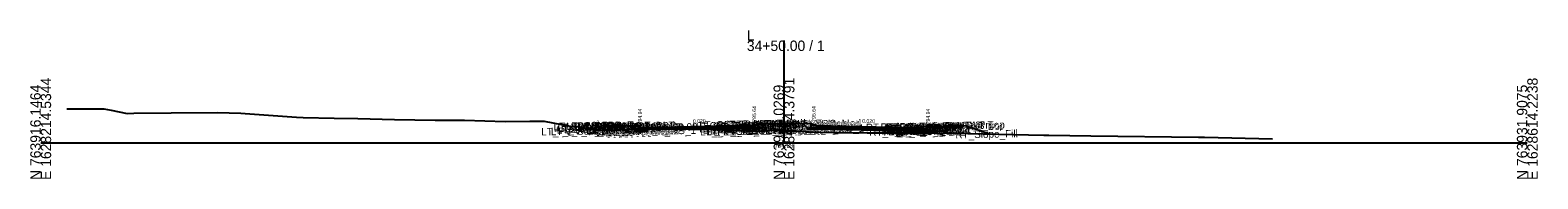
# Model space of a CAD drawing. Extents: x -26 to 4403, y -510 to 9556.
# Drawn here: x 1997.2 to 2402.8, y 4490.3 to 4530.3 of the extents above; entities that cross this region are included whole.
import ezdxf

# ---------------------------------------------------------------- set-up
doc = ezdxf.new("R2010")
doc.units = 0
for name, color, linetype in [('Default', 7, 'Continuous'), ('Exist CMT Pavement', 7, 'Continuous'), ('Exist Cross Section Cell', 7, 'Continuous'), ('Exist XS Center Line Elevation Label', 7, 'Continuous'), ('Exist XS Ground Line', 7, 'Continuous'), ('Prop CMT Conc Surface', 7, 'Continuous'), ('Prop CMT Concrete Structures', 7, 'Continuous'), ('Prop CMT Pvmt Course 1', 7, 'Continuous'), ('Prop CMT Pvmt Course 1 CG', 7, 'Continuous'), ('Prop CMT Pvmt Course 2', 7, 'Continuous'), ('Prop CMT Pvmt Course 2 Wedge', 7, 'Continuous'), ('Prop CMT Pvmt Course 3', 7, 'Continuous'), ('Prop CMT Pvmt Course 3 Wedge', 7, 'Continuous'), ('Prop CMT Pvmt Surface', 7, 'Continuous'), ('Prop CMT Slope Grass', 7, 'Continuous'), ('Prop CMT Subgrade Earthwork', 7, 'Continuous'), ('Prop XS Hydro Elevations', 7, 'Continuous'), ('Prop XS SE Text', 7, 'Continuous'), ('Prop XS Side Slope Text', 7, 'Continuous'), ('Scratch_Level_0', 7, 'Continuous')]:
    doc.layers.add(name, color=color, linetype=linetype)

msp = doc.modelspace()

# ---------------------------------------------------------------- linework, layer by layer
at = {"layer": 'Exist CMT Pavement'}
for points in [[(2163.26, 4503.69), (2168.79, 4503.73), (2171.81, 4503.75), (2174.71, 4503.69), (2181.6, 4503.54), (2184.34, 4503.45), (2190.83, 4503.23)], [(2190.83, 4503.23), (2190.83, 4503.23)]]:
    msp.add_lwpolyline(points, dxfattribs=at)
at = {"layer": 'Exist Cross Section Cell'}
for p, q in [((2200, 4500), (2200, 4527.48)), ((2000, 4500), (2200, 4500)), ((2200, 4500), (2400, 4500))]:
    msp.add_line(p, q, dxfattribs=at)
at = {"layer": 'Exist XS Ground Line'}
msp.add_lwpolyline([(2007.04, 4509.15), (2007.6, 4509.11), (2008.05, 4509.1), (2012.66, 4509.09), (2012.97, 4509.1), (2016.98, 4509.12), (2018.93, 4508.76), (2023.24, 4507.91), (2025.05, 4507.94), (2035.09, 4508.04), (2047.58, 4508.14), (2053.83, 4507.97), (2054.98, 4507.87), (2068.86, 4506.89), (2070.66, 4506.83), (2079, 4506.63), (2085.35, 4506.56), (2095.16, 4506.28), (2106.12, 4506.08), (2114.04, 4506.1), (2124.98, 4505.76), (2131.6, 4505.85), (2135.51, 4505.8), (2142.49, 4504.45), (2144.81, 4504.29), (2149.19, 4503.49), (2149.71, 4503.26), (2158.03, 4503.55), (2161.61, 4503.68), (2168.79, 4503.73), (2171.81, 4503.75), (2174.71, 4503.69), (2181.6, 4503.54), (2184.34, 4503.45), (2190.83, 4503.23), (2191.5, 4503.16), (2191.98, 4503.09), (2196.97, 4503.41), (2199.37, 4503.37), (2200, 4503.29), (2202.5, 4503), (2205.56, 4503.13), (2206.69, 4502.95), (2213.19, 4502.77), (2214.38, 4502.74), (2222.34, 4502.71), (2237.03, 4502.71), (2238.11, 4502.71), (2239.53, 4502.69), (2241.3, 4502.65), (2269.94, 4502.03), (2271.25, 4502.01), (2282.58, 4501.88), (2311.49, 4501.55), (2312.57, 4501.52), (2313.17, 4501.51), (2331.4, 4501.05)], dxfattribs=at)
at = {"layer": 'Prop CMT Conc Surface'}
for points in [[(2156.75, 4504.53), (2151.75, 4504.63)], [(2161.25, 4503.94), (2161.25, 4504.44), (2160.75, 4504.44)], [(2163.25, 4504.06), (2161.25, 4503.94)], [(2191.25, 4504.62), (2192, 4504.64), (2192, 4504.8), (2192.76, 4505.05)], [(2208.75, 4504.62), (2208, 4504.64), (2208, 4504.8), (2207.24, 4505.05)], [(2236.75, 4504.06), (2238.75, 4503.94)], [(2238.75, 4503.94), (2238.75, 4504.44), (2239.25, 4504.44)], [(2243.25, 4504.53), (2248.25, 4504.63)]]:
    msp.add_lwpolyline(points, dxfattribs=at)
at = {"layer": 'Prop CMT Concrete Structures'}
for points in [[(2151.75, 4504.3), (2151.75, 4504.63)], [(2151.75, 4504.63), (2156.75, 4504.53)], [(2156.75, 4504.2), (2151.75, 4504.3)], [(2156.75, 4504.53), (2156.75, 4504.2)], [(2163.25, 4504.06), (2161.25, 4503.94), (2161.25, 4504.44), (2160.75, 4504.44)], [(2160.75, 4504.44), (2160.75, 4503.43), (2163.25, 4503.48)], [(2163.25, 4503.48), (2163.25, 4504.06)], [(2191.25, 4504.62), (2192, 4504.64), (2192, 4504.8), (2192.76, 4505.05)], [(2191.25, 4504.04), (2191.25, 4504.62)], [(2192.76, 4504.07), (2191.25, 4504.04)], [(2192.76, 4505.05), (2192.76, 4504.07)], [(2208.75, 4504.62), (2208, 4504.64), (2208, 4504.8), (2207.24, 4505.05)], [(2207.24, 4505.05), (2207.24, 4504.07)], [(2207.24, 4504.07), (2208.75, 4504.04)], [(2208.75, 4504.04), (2208.75, 4504.62)], [(2236.75, 4504.06), (2238.75, 4503.94), (2238.75, 4504.44), (2239.25, 4504.44)], [(2239.25, 4504.44), (2239.25, 4503.43), (2236.75, 4503.48)], [(2236.75, 4503.48), (2236.75, 4504.06)], [(2248.25, 4504.63), (2243.25, 4504.53)], [(2243.25, 4504.53), (2243.25, 4504.2)], [(2243.25, 4504.2), (2248.25, 4504.3)], [(2248.25, 4504.3), (2248.25, 4504.63)]]:
    msp.add_lwpolyline(points, dxfattribs=at)
at = {"layer": 'Prop CMT Pvmt Course 1'}
for points in [[(2191.25, 4504.62), (2163.25, 4504.06)], [(2163.25, 4503.81), (2190.83, 4504.36), (2191.25, 4504.37)], [(2163.25, 4504.06), (2163.25, 4503.81), (2163.25, 4503.81)], [(2191.25, 4504.37), (2191.25, 4504.62)], [(2208.75, 4504.62), (2236.75, 4504.06)], [(2208.75, 4504.37), (2208.75, 4504.62)], [(2236.75, 4503.81), (2208.75, 4504.37)], [(2208.75, 4504.37), (2208.75, 4504.37), (2208.75, 4504.37)], [(2236.75, 4504.06), (2236.75, 4503.81)]]:
    msp.add_lwpolyline(points, dxfattribs=at)
at = {"layer": 'Prop CMT Pvmt Course 1 CG'}
for points in [[(2163.25, 4503.48), (2160.25, 4503.42), (2159.91, 4503.08)], [(2159.91, 4503.08), (2163.25, 4503.15)], [(2163.25, 4503.15), (2163.25, 4503.48)], [(2191.25, 4504.04), (2193.26, 4504.08), (2193.59, 4503.75)], [(2191.25, 4503.71), (2191.25, 4504.04)], [(2193.59, 4503.75), (2191.25, 4503.71)], [(2208.75, 4504.04), (2206.74, 4504.08), (2206.41, 4503.75)], [(2206.41, 4503.75), (2208.75, 4503.71)], [(2208.75, 4503.71), (2208.75, 4504.04)], [(2236.75, 4503.48), (2239.75, 4503.42), (2240.09, 4503.08)], [(2236.75, 4503.15), (2236.75, 4503.48)], [(2240.09, 4503.08), (2236.75, 4503.15)]]:
    msp.add_lwpolyline(points, dxfattribs=at)
at = {"layer": 'Prop CMT Pvmt Course 2'}
for points in [[(2163.25, 4503.48), (2163.25, 4503.48), (2163.25, 4503.81), (2163.25, 4503.81)], [(2163.25, 4503.81), (2163.25, 4503.48)], [(2191.25, 4504.37), (2190.83, 4504.36)], [(2190.83, 4504.36), (2190.83, 4504.03)], [(2190.83, 4504.03), (2191.25, 4504.04)], [(2191.25, 4504.04), (2191.25, 4504.37)], [(2208.75, 4504.04), (2208.75, 4504.37)], [(2208.75, 4504.37), (2236.75, 4503.81)], [(2236.75, 4503.48), (2208.75, 4504.04)], [(2236.75, 4503.81), (2236.75, 4503.48)]]:
    msp.add_lwpolyline(points, dxfattribs=at)
at = {"layer": 'Prop CMT Pvmt Course 2 Wedge'}
for points in [[(2163.25, 4503.81), (2168.79, 4503.92), (2171.81, 4503.98), (2174.71, 4504.04), (2181.6, 4504.18), (2184.34, 4504.23), (2190.83, 4504.36)], [(2163.25, 4503.69), (2163.25, 4503.81)], [(2190.83, 4504.03), (2184.34, 4503.9), (2181.6, 4503.85), (2174.71, 4503.71), (2174.23, 4503.7), (2171.81, 4503.75), (2168.79, 4503.73), (2163.26, 4503.69)], [(2190.83, 4504.36), (2190.83, 4504.03), (2190.83, 4504.03)]]:
    msp.add_lwpolyline(points, dxfattribs=at)
at = {"layer": 'Prop CMT Pvmt Course 3'}
for points in [[(2163.25, 4503.48), (2163.25, 4503.48), (2163.25, 4503.15), (2163.25, 4503.15)], [(2163.25, 4503.15), (2163.25, 4503.48)], [(2191.25, 4504.04), (2190.83, 4504.03)], [(2190.83, 4504.03), (2190.83, 4503.7)], [(2190.83, 4503.7), (2191.25, 4503.71)], [(2191.25, 4503.71), (2191.25, 4504.04)], [(2208.75, 4504.04), (2236.75, 4503.48)], [(2208.75, 4503.71), (2208.75, 4504.04)], [(2236.75, 4503.15), (2208.75, 4503.71)], [(2236.75, 4503.48), (2236.75, 4503.15)]]:
    msp.add_lwpolyline(points, dxfattribs=at)
at = {"layer": 'Prop CMT Pvmt Course 3 Wedge'}
for points in [[(2174.23, 4503.7), (2174.71, 4503.71)], [(2190.83, 4503.23), (2184.34, 4503.45), (2181.6, 4503.54), (2174.71, 4503.69), (2174.23, 4503.7)], [(2174.71, 4503.71), (2181.6, 4503.85), (2184.34, 4503.9), (2190.83, 4504.03)], [(2190.83, 4504.03), (2190.83, 4503.23), (2190.83, 4503.23)]]:
    msp.add_lwpolyline(points, dxfattribs=at)
at = {"layer": 'Prop CMT Pvmt Surface'}
for points in [[(2191.25, 4504.62), (2163.25, 4504.06)], [(2208.75, 4504.62), (2236.75, 4504.06)]]:
    msp.add_lwpolyline(points, dxfattribs=at)
at = {"layer": 'Prop CMT Slope Grass'}
for points in [[(2160.75, 4504.44), (2151.25, 4504.63), (2148.31, 4503.65)], [(2192.76, 4505.05), (2200, 4505.2)], [(2207.24, 4505.05), (2200, 4505.2)], [(2239.25, 4504.44), (2248.75, 4504.63), (2255.63, 4502.34)]]:
    msp.add_lwpolyline(points, dxfattribs=at)
at = {"layer": 'Prop CMT Subgrade Earthwork'}
for points in [[(2163.25, 4503.15), (2159.91, 4503.08), (2158.5, 4504.49)], [(2163.25, 4503.15), (2163.26, 4503.69)], [(2163.25, 4503.15), (2163.25, 4503.48)], [(2163.25, 4503.15), (2163.25, 4503.15)], [(2163.25, 4503.15), (2163.25, 4503.15)], [(2191.25, 4503.71), (2190.83, 4503.7)], [(2190.83, 4503.7), (2190.83, 4503.23)], [(2193.59, 4503.75), (2191.25, 4503.71)], [(2191.25, 4503.71), (2191.25, 4503.71)], [(2194.93, 4505.1), (2193.59, 4503.75)], [(2205.07, 4505.1), (2206.41, 4503.75)], [(2206.41, 4503.75), (2208.75, 4503.71)], [(2208.75, 4503.71), (2236.75, 4503.15)], [(2208.75, 4503.71), (2208.75, 4503.71)], [(2208.75, 4503.71), (2208.75, 4503.71)], [(2236.75, 4503.15), (2240.09, 4503.08), (2241.5, 4504.49)], [(2236.75, 4503.15), (2236.75, 4503.15)]]:
    msp.add_lwpolyline(points, dxfattribs=at)

# ---------------------------------------------------------------- texts
at = {"layer": 'Default'}
msp.add_text('-', height=0.0001, dxfattribs=at).set_placement((2000, 4500))
at = {"layer": 'Exist Cross Section Cell'}
for s, p in [('34+50.00 / 1', (2190, 4524.68)), ('L', (2190, 4527.48))]:
    msp.add_text(s, height=2.8, dxfattribs=at).set_placement(p)
for s, p in [('N 763916.1464', (2000, 4490)), ('E 1628214.5344', (2002.8, 4490)), ('N 763924.0269', (2200, 4490)), ('E 1628414.3791', (2202.8, 4490)), ('N 763931.9075', (2400, 4490)), ('E 1628614.2238', (2402.8, 4490))]:
    msp.add_text(s, height=2.8, rotation=90, dxfattribs=at).set_placement(p)
at = {"layer": 'Exist XS Center Line Elevation Label'}
msp.add_text('794.29', height=1.2, dxfattribs=at).set_placement((2197.48, 4498.69))
at = {"layer": 'Prop XS Hydro Elevations'}
for s, p in [('794.94', (2161.75, 4504.94)), ('795.64', (2192.5, 4505.64)), ('795.64', (2208.5, 4505.64)), ('794.94', (2239.25, 4504.94))]:
    msp.add_text(s, height=1, rotation=90, dxfattribs=at).set_placement(p)
at = {"layer": 'Prop XS SE Text'}
for rotation, p in [(1.1458, (2175.48, 4505.31)), (358.8543, (2221.02, 4505.38))]:
    msp.add_text('0.020', height=1, rotation=rotation, dxfattribs=at).set_placement(p)
at = {"layer": 'Prop XS Side Slope Text'}
for rotation, p in [(18.4333, (2148.79, 4504.6)), (341.5634, (2251.68, 4504.45))]:
    msp.add_text('3:1', height=1, rotation=rotation, dxfattribs=at).set_placement(p)
at = {"layer": 'Scratch_Level_0'}
for s, p in [('LT_PV_Sub_Tie_Out', (2134.68, 4501.96)), ('LT_PV_OEEOP_EG', (2137.28, 4502.02)), ('LT_SDWK_Out_Top', (2138.01, 4503.36)), ('LT_SDWK_Out_Bot', (2138.04, 4503.02)), ('LT_Slope_Fill', (2138.85, 4502.46)), ('LT_Sub_Trench_Out_DLT', (2139.09, 4503.1)), ('LT_CSLP_Pnt', (2141.45, 4503.44)), ('34+50.00', (2144.64, 4503.5)), ('LT_SDWK_In_Top', (2144.63, 4503.29)), ('LT_SDWK_In_Bot', (2144.66, 4502.96)), ('LT_CG1_Shelf_Out', (2146.82, 4502.15)), ('LT_CG_Top_Face', (2148.53, 4503.19)), ('LT_CG_Top_BOC', (2149.06, 4503.21)), ('LT_CG_Bot_BOC', (2149.09, 4502.2)), ('LT_Sub_OEOT_CG_1', (2149.49, 4501.87)), ('LT_CG_Top_Gut', (2149.51, 4502.71)), ('LT_Sub_OEOP', (2150.04, 4501.88)), ('34+50.00', (2152.54, 4503.34)), ('LT_Sub_OEEOP', (2152.49, 4501.93)), ('LT_PV2_OEEOP', (2152.58, 4502.6)), ('LT_PV3_OEEOP', (2152.58, 4502.27)), ('LT_CG_Bot_IE', (2153.19, 4502.28)), ('LT_Sub_OEOT', (2153.35, 4501.95)), ('LT_PV2_OEOT', (2153.45, 4502.62)), ('LT_PV3_OEOT', (2153.45, 4502.28)), ('LT_PV1_OEOT', (2154.01, 4502.88)), ('34+50.00', (2155.53, 4502.87)), ('34+50.00', (2165.54, 4503.11)), ('LT_CG_Top_Face_Med', (2175.39, 4503.47)), ('LT_CG_Top_Gut_Med', (2176.37, 4503.33)), ('LT_CG_Top_BOC_Med', (2177.18, 4503.74)), ('LT_CG_Bot_BOC_Med', (2177.21, 4502.76)), ('LT_CG_Bot_IE_Med', (2177.34, 4502.76)), ('LT_PV_Sub_Tie_In', (2177.42, 4501.97)), ('LT_Sub_IEOT_CG_1', (2178.14, 4502.44)), ('LT_PV_IEEOP_EG', (2179.04, 4502)), ('LT_Sub_IEEOP', (2180.71, 4502.49)), ('LT_PV2_IEEOP', (2180.8, 4503.16)), ('LT_PV3_IEEOP', (2180.8, 4502.83)), ('LT_CG1_Shelf_In', (2181.46, 4502.84)), ('LT_Sub_PGL', (2182.39, 4502.53)), ('LT_PV2_PGL', (2182.48, 4503.2)), ('LT_PV3_PGL', (2182.48, 4502.86)), ('LT_PV1_PGL', (2183.05, 4503.46)), ('LT_Sub_DLT_In', (2183.9, 4503.88)), ('LT_Sub_IEOP', (2184.36, 4502.57)), ('34+50.00', (2184.8, 4503.49)), ('MD_Crown Point', (2187.09, 4503.94)), ('34+50.00', (2187.23, 4503.94)), ('RT_CG_Top_Face_Med', (2191.35, 4503.47)), ('RT_CG_Top_BOC_Med', (2191.61, 4503.74)), ('RT_CG_Bot_BOC_Med', (2191.64, 4502.76)), ('34+50.00', (2192.35, 4504.05)), ('RT_CG_Top_Gut_Med', (2192.32, 4503.32)), ('RT_Sub_DLT_In', (2193.99, 4503.88)), ('RT_CG_Bot_IE_Med', (2194.79, 4502.76)), ('RT_CG1_Shelf_In', (2194.89, 4502.84)), ('RT_Sub_IEOT_CG_1', (2195.59, 4502.44)), ('RT_Sub_IEOP', (2197.14, 4502.57)), ('RT_Sub_OEEOP', (2197.94, 4502.49)), ('RT_PV2_OEEOP', (2198.03, 4503.16)), ('RT_PV3_OEEOP', (2198.03, 4502.82)), ('RT_Sub_IEEOP', (2198.58, 4502.5)), ('RT_PV2_IEEOP', (2198.68, 4503.17)), ('34+50.00', (2199.73, 4503.93)), ('RT_Sub_PGL', (2199.84, 4502.53)), ('RT_PV2_PGL', (2199.94, 4503.2)), ('RT_PV1_PGL', (2200.5, 4503.46)), ('34+50.00', (2201.55, 4503.5)), ('RT_Sub_Trench_Out_DLT', (2222.04, 4503.1)), ('RT_Sub_OEOT_CG_1', (2222.95, 4501.87)), ('RT_CG_Top_Face', (2225.99, 4503.19)), ('RT_CG1_Shelf_Out', (2226.28, 4502.15)), ('RT_CG_Bot_IE', (2226.64, 4502.28)), ('RT_Sub_OEOT', (2226.8, 4501.95)), ('RT_PV2_OEOT', (2226.9, 4502.62)), ('RT_PV3_OEOT', (2226.9, 4502.28)), ('RT_CG_Top_Gut', (2226.96, 4502.71)), ('RT_PV1_OEOT', (2227.47, 4502.88)), ('RT_CG_Top_BOC', (2227.51, 4503.21)), ('RT_CG_Bot_BOC', (2227.54, 4502.19)), ('34+50.00', (2228.87, 4502.95)), ('34+50.00', (2230.13, 4502.92)), ('RT_Sub_OEOP', (2230.18, 4501.88)), ('RT_SDWK_In_Top', (2231.08, 4503.29)), ('RT_SDWK_In_Bot', (2231.12, 4502.96)), ('34+50.00', (2234.41, 4503.35)), ('RT_SDWK_Out_Top', (2234.46, 4503.36)), ('RT_SDWK_Out_Bot', (2234.49, 4503.02)), ('RT_CSLP_Pnt', (2238.9, 4503.44)), ('34+50.00', (2241.73, 4503.5)), ('RT_Slope_Fill', (2246.13, 4501.15))]:
    msp.add_text(s, height=2, rotation=1.1458, dxfattribs=at).set_placement(p)

doc.saveas('drawing.dxf')
